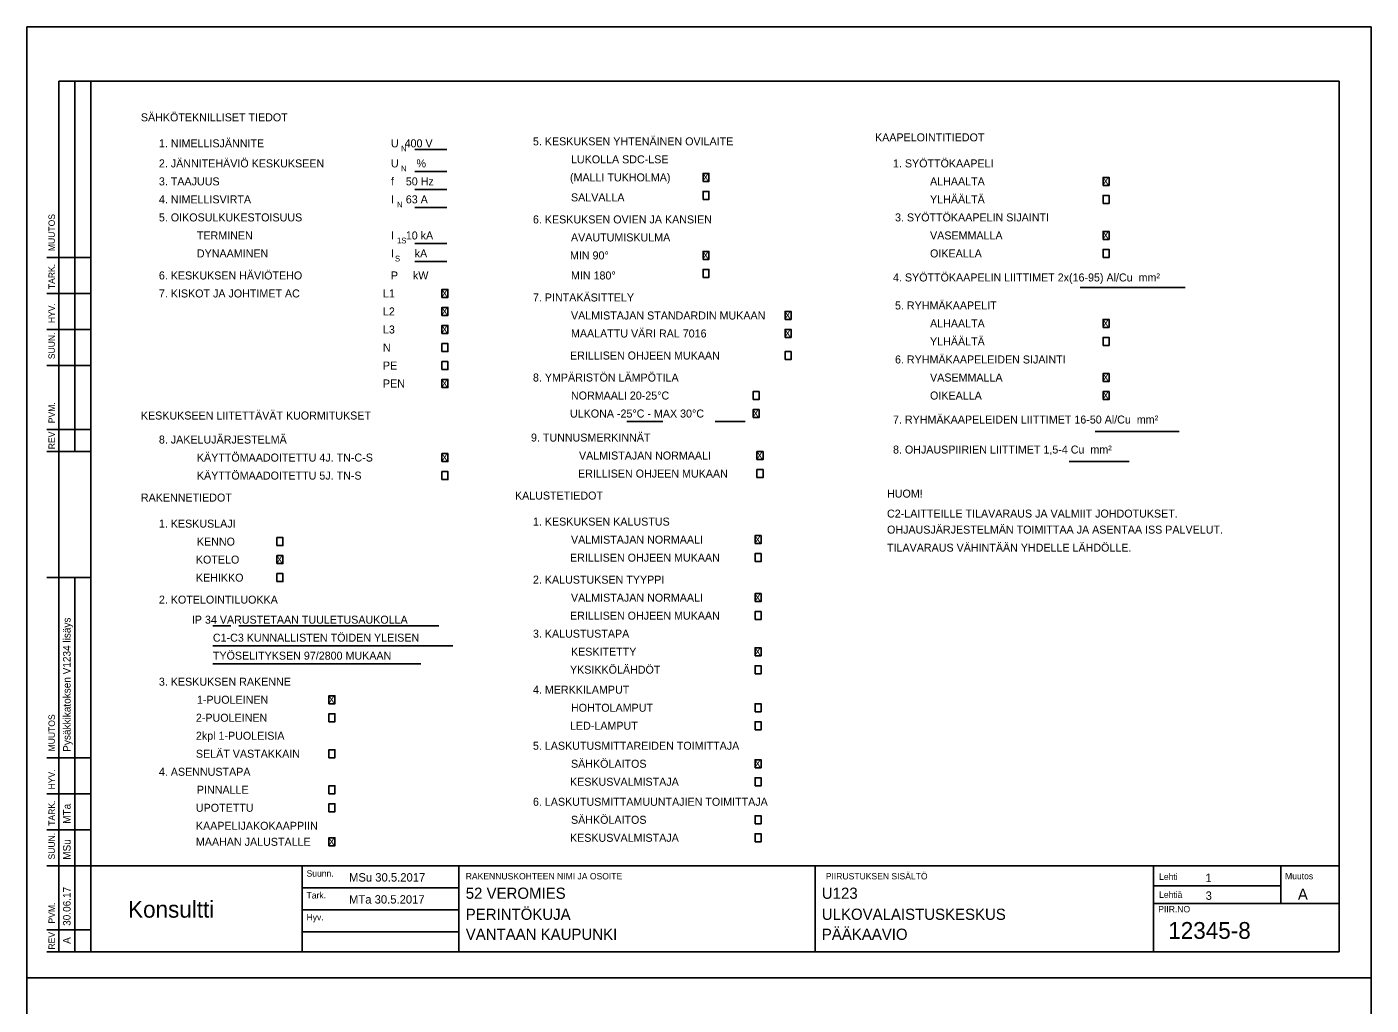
# Model space of a CAD drawing. Extents: x 0 to 420, y -594 to 297.
# Drawn here: x 0 to 420, y -8.5 to 297 of the extents above; entities that cross this region are included whole.
import ezdxf

# ---------------------------------------------------------------- set-up
doc = ezdxf.new("R2010")
doc.units = 0
doc.layers.add('TEKSTI', color=7, linetype='Continuous')

msp = doc.modelspace()

# ---------------------------------------------------------------- linework, layer by layer
for p, q in [((0, 297), (0, 0)), ((420, 297), (0, 297)), ((420, 0), (420, 297)), ((10, 280), (10, 8.12)), ((15, 164.38), (15, 280)), ((20, 280), (20, 8.12)), ((410, 280), (20, 280)), ((410, 8.12), (410, 280)), ((15, 8.12), (15, 125)), ((410, 32.5), (410, 85)), ((20, 35), (410, 35)), ((86, 35), (86, 8.12)), ((135, 35), (135, 8.12)), ((246.25, 8.12), (246.25, 35)), ((352, 8.12), (352, 35)), ((391.75, 23.22), (391.75, 35)), ((86, 28.12), (135, 28.12)), ((351.88, 28.75), (391.75, 28.75)), ((86, 21.25), (135, 21.25)), ((351.88, 23.2), (410, 23.2)), ((86, 14.38), (135, 14.38)), ((20, 8.12), (410, 8.12)), ((0, 0), (0, -297)), ((420, 0), (0, 0)), ((420, -297), (420, 0))]:
    msp.add_line(p, q)
for points in [[(10, 280), (20.14, 280)], [(121.25, 258.75), (131.25, 258.75)], [(121.25, 251.88), (131.25, 251.88)], [(211.25, 248.75), (213.12, 248.75), (213.12, 251.25), (211.25, 251.25), (211.25, 248.75)], [(336.25, 247.5), (338.12, 247.5), (338.12, 250), (336.25, 250), (336.25, 247.5)], [(121.25, 246.25), (131.25, 246.25)], [(211.25, 243.12), (213.12, 243.12), (213.12, 245.62), (211.25, 245.62), (211.25, 243.12)], [(336.25, 241.88), (338.12, 241.88), (338.12, 244.38), (336.25, 244.38), (336.25, 241.88)], [(121.25, 240.62), (131.25, 240.62)], [(336.25, 230.62), (338.12, 230.62), (338.12, 233.12), (336.25, 233.12), (336.25, 230.62)], [(121.25, 229.38), (131.25, 229.38)], [(211.25, 224.38), (213.12, 224.38), (213.12, 226.88), (211.25, 226.88), (211.25, 224.38)], [(336.25, 225), (338.12, 225), (338.12, 227.5), (336.25, 227.5), (336.25, 225)], [(6.25, 225), (20, 225)], [(121.25, 223.75), (131.25, 223.75)], [(211.25, 218.75), (213.12, 218.75), (213.12, 221.25), (211.25, 221.25), (211.25, 218.75)], [(129.69, 212.5), (131.56, 212.5), (131.56, 215), (129.69, 215), (129.69, 212.5)], [(329.06, 215.62), (361.88, 215.62)], [(6.25, 213.75), (20, 213.75)], [(129.69, 206.88), (131.56, 206.88), (131.56, 209.38), (129.69, 209.38), (129.69, 206.88)], [(236.88, 205.62), (238.75, 205.62), (238.75, 208.12), (236.88, 208.12), (236.88, 205.62)], [(6.25, 202.5), (20, 202.5)], [(129.69, 201.25), (131.56, 201.25), (131.56, 203.75), (129.69, 203.75), (129.69, 201.25)], [(236.88, 200), (238.75, 200), (238.75, 202.5), (236.88, 202.5), (236.88, 200)], [(336.25, 203.12), (338.12, 203.12), (338.12, 205.62), (336.25, 205.62), (336.25, 203.12)], [(129.69, 195.62), (131.56, 195.62), (131.56, 198.12), (129.69, 198.12), (129.69, 195.62)], [(336.25, 197.5), (338.12, 197.5), (338.12, 200), (336.25, 200), (336.25, 197.5)], [(236.88, 193.12), (238.75, 193.12), (238.75, 195.62), (236.88, 195.62), (236.88, 193.12)], [(6.25, 191.25), (20, 191.25)], [(129.69, 190), (131.56, 190), (131.56, 192.5), (129.69, 192.5), (129.69, 190)], [(129.69, 184.38), (131.56, 184.38), (131.56, 186.88), (129.69, 186.88), (129.69, 184.38)], [(336.25, 186.25), (338.12, 186.25), (338.12, 188.75), (336.25, 188.75), (336.25, 186.25)], [(226.88, 180.62), (228.75, 180.62), (228.75, 183.12), (226.88, 183.12), (226.88, 180.62)], [(336.25, 180.62), (338.12, 180.62), (338.12, 183.12), (336.25, 183.12), (336.25, 180.62)], [(226.88, 175), (228.75, 175), (228.75, 177.5), (226.88, 177.5), (226.88, 175)], [(187.5, 173.75), (198.75, 173.75)], [(215, 173.75), (224.38, 173.75)], [(6.25, 171.25), (20, 171.25)], [(333.75, 170.62), (360, 170.62)], [(6.25, 164.38), (20.14, 164.38)], [(228.12, 161.88), (230, 161.88), (230, 164.38), (228.12, 164.38), (228.12, 161.88)], [(129.69, 161.25), (131.56, 161.25), (131.56, 163.75), (129.69, 163.75), (129.69, 161.25)], [(325.62, 161.25), (344.38, 161.25)], [(129.69, 155.62), (131.56, 155.62), (131.56, 158.12), (129.69, 158.12), (129.69, 155.62)], [(228.12, 156.25), (230, 156.25), (230, 158.75), (228.12, 158.75), (228.12, 156.25)], [(78.12, 135), (80, 135), (80, 137.5), (78.12, 137.5), (78.12, 135)], [(227.5, 135.62), (229.38, 135.62), (229.38, 138.12), (227.5, 138.12), (227.5, 135.62)], [(78.12, 129.38), (80, 129.38), (80, 131.88), (78.12, 131.88), (78.12, 129.38)], [(227.5, 130), (229.38, 130), (229.38, 132.5), (227.5, 132.5), (227.5, 130)], [(78.12, 123.75), (80, 123.75), (80, 126.25), (78.12, 126.25), (78.12, 123.75)], [(6.25, 125), (20, 125)], [(227.5, 117.5), (229.38, 117.5), (229.38, 120), (227.5, 120), (227.5, 117.5)], [(227.5, 111.88), (229.38, 111.88), (229.38, 114.38), (227.5, 114.38), (227.5, 111.88)], [(63.75, 110), (58.12, 110)], [(66.25, 110), (128.75, 110)], [(58.12, 103.75), (133.12, 103.75)], [(227.5, 100.62), (229.38, 100.62), (229.38, 103.12), (227.5, 103.12), (227.5, 100.62)], [(58.12, 98.12), (123.12, 98.12)], [(227.5, 95), (229.38, 95), (229.38, 97.5), (227.5, 97.5), (227.5, 95)], [(94.38, 85.62), (96.25, 85.62), (96.25, 88.12), (94.38, 88.12), (94.38, 85.62)], [(227.5, 83.12), (229.38, 83.12), (229.38, 85.62), (227.5, 85.62), (227.5, 83.12)], [(94.38, 80), (96.25, 80), (96.25, 82.5), (94.38, 82.5), (94.38, 80)], [(227.5, 77.5), (229.38, 77.5), (229.38, 80), (227.5, 80), (227.5, 77.5)], [(6.25, 68.75), (20, 68.75)], [(94.38, 68.75), (96.25, 68.75), (96.25, 71.25), (94.38, 71.25), (94.38, 68.75)], [(227.5, 65.62), (229.38, 65.62), (229.38, 68.12), (227.5, 68.12), (227.5, 65.62)], [(94.38, 57.5), (96.25, 57.5), (96.25, 60), (94.38, 60), (94.38, 57.5)], [(227.5, 60), (229.38, 60), (229.38, 62.5), (227.5, 62.5), (227.5, 60)], [(6.25, 57.5), (20, 57.5)], [(94.38, 51.88), (96.25, 51.88), (96.25, 54.38), (94.38, 54.38), (94.38, 51.88)], [(227.5, 48.12), (229.38, 48.12), (229.38, 50.62), (227.5, 50.62), (227.5, 48.12)], [(6.25, 46.25), (20, 46.25)], [(94.38, 41.25), (96.25, 41.25), (96.25, 43.75), (94.38, 43.75), (94.38, 41.25)], [(227.5, 42.5), (229.38, 42.5), (229.38, 45), (227.5, 45), (227.5, 42.5)], [(6.25, 35), (20, 35)], [(6.25, 15), (20, 15)], [(20, 8.12), (6.25, 8.12)], [(0, 0), (420, 0)]]:
    msp.add_lwpolyline(points)

# ---------------------------------------------------------------- texts
for s, height, p in [('SÄHKÖTEKNILLISET TIEDOT', 2.5, (35.62, 267.5)), ('1. NIMELLISJÄNNITE', 2.5, (41.25, 259.38)), ('U  400 V', 2.5, (113.75, 259.38)), ('5. KESKUKSEN YHTENÄINEN OVILAITE', 2.5, (158.12, 260)), ('KAAPELOINTITIEDOT', 2.5, (265, 261.25)), ('N', 1.8, (116.88, 258.12)), ('LUKOLLA SDC-LSE', 2.5, (170, 254.38)), ('2. JÄNNITEHÄVIÖ KESKUKSEEN', 2.5, (41.25, 253.12)), ('U      %%%', 2.5, (113.75, 253.12)), ('N', 1.8, (116.88, 251.88)), ('1. SYÖTTÖKAAPELI', 2.5, (270.62, 253.12)), ('3. TAAJUUS', 2.5, (41.25, 247.5)), ('f    50 Hz', 2.5, (113.75, 247.5)), ('(MALLI TUKHOLMA)', 2.5, (169.69, 248.75)), ('X', 2.5, (210.94, 248.75)), ('ALHAALTA', 2.5, (282.19, 247.5)), ('X', 2.5, (335.94, 247.5)), ('4. NIMELLISVIRTA', 2.5, (41.25, 241.88)), ('I    63 A', 2.5, (113.75, 241.88)), ('SALVALLA', 2.5, (170, 242.5)), ('YLHÄÄLTÄ', 2.5, (282.19, 241.88)), ('N', 1.8, (115.62, 240.62)), ('5. OIKOSULKUKESTOISUUS', 2.5, (41.25, 236.25)), ('6. KESKUKSEN OVIEN JA KANSIEN', 2.5, (158.12, 235.62)), ('3. SYÖTTÖKAAPELIN SIJAINTI', 2.5, (271.25, 236.25)), ('TERMINEN', 2.5, (53.12, 230.62)), ('I    10 kA', 2.5, (113.75, 230.62)), ('1S', 1.8, (115.62, 229.38)), ('AVAUTUMISKULMA', 2.5, (170, 230)), ('VASEMMALLA', 2.5, (282.19, 230.62)), ('X', 2.5, (335.94, 230.62)), ('DYNAAMINEN', 2.5, (53.12, 225)), ('I       kA', 2.5, (113.75, 225)), ('MIN 90°', 2.5, (169.69, 224.38)), ('X', 2.5, (210.94, 224.38)), ('OIKEALLA', 2.5, (282.19, 225)), ('S', 1.8, (115, 223.75)), ('6. KESKUKSEN HÄVIÖTEHO', 2.5, (41.25, 218.12)), ('P     kW', 2.5, (113.75, 218.12)), ('MIN 180°', 2.5, (170, 218.12)), ('4. SYÖTTÖKAAPELIN LIITTIMET 2x(16-95) Al/Cu  mm²  ', 2.5, (270.62, 217.5)), ('7. KISKOT JA JOHTIMET AC', 2.5, (41.25, 212.5)), ('L1', 2.5, (111.25, 212.5)), ('X', 2.5, (129.38, 212.5)), ('7. PINTAKÄSITTELY', 2.5, (158.12, 211.25)), ('5. RYHMÄKAAPELIT', 2.5, (271.25, 208.75)), ('L2', 2.5, (111.25, 206.88)), ('X', 2.5, (129.38, 206.88)), ('VALMISTAJAN STANDARDIN MUKAAN', 2.5, (170, 205.62)), ('X', 2.5, (236.56, 205.62)), ('L3', 2.5, (111.25, 201.25)), ('X', 2.5, (129.38, 201.25)), ('MAALATTU VÄRI RAL 7016', 2.5, (170, 200)), ('X', 2.5, (236.56, 200)), ('ALHAALTA', 2.5, (282.19, 203.12)), ('X', 2.5, (335.94, 203.12)), ('N', 2.5, (111.25, 195.62)), ('YLHÄÄLTÄ', 2.5, (282.19, 197.5)), ('ERILLISEN OHJEEN MUKAAN', 2.5, (169.69, 193.12)), ('6. RYHMÄKAAPELEIDEN SIJAINTI', 2.5, (271.25, 191.88)), ('PE', 2.5, (111.25, 190)), ('8. YMPÄRISTÖN LÄMPÖTILA', 2.5, (158.12, 186.25)), ('PEN', 2.5, (111.25, 184.38)), ('X', 2.5, (129.38, 184.38)), ('VASEMMALLA', 2.5, (282.19, 186.25)), ('X', 2.5, (335.94, 186.25)), ('NORMAALI 20-25°C', 2.5, (170, 180.62)), ('OIKEALLA', 2.5, (282.19, 180.62)), ('X', 2.5, (335.94, 180.62)), ('KESKUKSEEN LIITETTÄVÄT KUORMITUKSET', 2.5, (35.62, 174.38)), ('ULKONA -25°C - MAX 30°C', 2.5, (169.69, 175)), ('X', 2.5, (226.56, 175)), ('7. RYHMÄKAAPELEIDEN LIITTIMET 16-50 Al/Cu  mm²  ', 2.5, (270.62, 173.12)), ('8. JAKELUJÄRJESTELMÄ', 2.5, (41.25, 166.88)), ('9. TUNNUSMERKINNÄT', 2.5, (157.5, 167.5)), ('KÄYTTÖMAADOITETTU 4J. TN-C-S', 2.5, (53.12, 161.25)), ('VALMISTAJAN NORMAALI', 2.5, (172.5, 161.88)), ('X', 2.5, (227.81, 161.88)), ('8. OHJAUSPIIRIEN LIITTIMET 1,5-4 Cu  mm²  ', 2.5, (270.62, 163.75)), ('X', 2.5, (129.38, 161.25)), ('KÄYTTÖMAADOITETTU 5J. TN-S', 2.5, (53.12, 155.62)), ('ERILLISEN OHJEEN MUKAAN', 2.5, (172.19, 156.25)), ('RAKENNETIEDOT', 2.5, (35.62, 148.75)), ('KALUSTETIEDOT', 2.5, (152.5, 149.38)), ('HUOM!', 2.5, (268.75, 150)), ('1. KESKUSLAJI', 2.5, (41.25, 140.62)), ('1. KESKUKSEN KALUSTUS', 2.5, (158.12, 141.25)), ('C2-LAITTEILLE TILAVARAUS JA VALMIIT JOHDOTUKSET.', 2.5, (268.75, 143.75)), ('OHJAUSJÄRJESTELMÄN TOIMITTAA JA ASENTAA ISS PALVELUT.', 2.5, (268.75, 138.75)), ('KENNO', 2.5, (53.12, 135)), ('VALMISTAJAN NORMAALI', 2.5, (170, 135.62)), ('X', 2.5, (227.19, 135.62)), ('TILAVARAUS VÄHINTÄÄN YHDELLE LÄHDÖLLE.', 2.5, (268.75, 133.12)), ('KOTELO', 2.5, (52.81, 129.38)), ('X', 2.5, (77.81, 129.38)), ('ERILLISEN OHJEEN MUKAAN', 2.5, (169.69, 130)), ('KEHIKKO', 2.5, (52.81, 123.75)), ('2. KALUSTUKSEN TYYPPI', 2.5, (158.12, 123.12)), ('2. KOTELOINTILUOKKA', 2.5, (41.25, 116.88)), ('VALMISTAJAN NORMAALI', 2.5, (170, 117.5)), ('X', 2.5, (227.19, 117.5)), ('ERILLISEN OHJEEN MUKAAN', 2.5, (169.69, 111.88)), (' IP 34 VARUSTETAAN TUULETUSAUKOLLA', 2.5, (50.62, 110.62)), ('C1-C3 KUNNALLISTEN TÖIDEN YLEISEN', 2.5, (58.12, 105)), ('3. KALUSTUSTAPA', 2.5, (158.12, 106.25)), ('TYÖSELITYKSEN 97/2800 MUKAAN', 2.5, (58.12, 99.38)), ('KESKITETTY', 2.5, (170, 100.62)), ('X', 2.5, (227.19, 100.62)), ('YKSIKKÖLÄHDÖT', 2.5, (169.69, 95)), ('3. KESKUKSEN RAKENNE', 2.5, (41.25, 91.25)), ('4. MERKKILAMPUT', 2.5, (158.12, 88.75)), ('1-PUOLEINEN', 2.5, (53.12, 85.62)), ('X', 2.5, (94.06, 85.62)), ('HOHTOLAMPUT', 2.5, (170, 83.12)), ('2-PUOLEINEN', 2.5, (52.81, 80)), ('LED-LAMPUT', 2.5, (169.69, 77.5)), ('2kpl 1-PUOLEISIA', 2.5, (52.81, 74.38)), ('SELÄT VASTAKKAIN', 2.5, (52.81, 68.75)), ('5. LASKUTUSMITTAREIDEN TOIMITTAJA', 2.5, (158.12, 71.25)), ('SÄHKÖLAITOS', 2.5, (170, 65.62)), ('X', 2.5, (227.19, 65.62)), ('4. ASENNUSTAPA', 2.5, (41.25, 63.12)), ('PINNALLE', 2.5, (53.12, 57.5)), ('KESKUSVALMISTAJA', 2.5, (169.69, 60)), ('6. LASKUTUSMITTAMUUNTAJIEN TOIMITTAJA', 2.5, (158.12, 53.75)), ('UPOTETTU', 2.5, (52.81, 51.88)), ('SÄHKÖLAITOS', 2.5, (170, 48.12)), ('KAAPELIJAKOKAAPPIIN', 2.5, (52.81, 46.25)), ('MAAHAN JALUSTALLE', 2.5, (52.81, 41.25)), ('X', 2.5, (94.06, 41.25)), ('KESKUSVALMISTAJA', 2.5, (169.69, 42.5)), ('Suunn.', 2, (87.38, 31.62)), ('MSu 30.5.2017', 2.625, (100.66, 30.08)), ('RAKENNUSKOHTEEN NIMI JA OSOITE', 2, (137.12, 30.75)), ('PIIRUSTUKSEN SISÄLTÖ', 2, (249.62, 30.75)), ('Lehti', 2, (353.75, 30.62)), ('1', 2.62, (368.21, 29.92)), ('Muutos', 2, (393.12, 30.79)), ('Tark.', 2, (87.38, 24.8)), ('MTa 30.5.2017', 2.625, (100.66, 23.2)), ('52 VEROMIES', 3.5, (137.12, 24.69)), ('U123', 3.5, (248.38, 24.69)), ('Lehtiä', 2, (353.75, 25)), ('3', 2.62, (368.31, 24.38)), ('A', 3.5, (397.12, 24.38)), ('Konsultti', 5.25, (31.62, 18.81)), ('PERINTÖKUJA', 3.5, (137.12, 18.12)), ('ULKOVALAISTUSKESKUS', 3.5, (248.38, 18.12)), ('PIIR.NO', 2, (353.5, 20.45)), ('Hyv.', 2, (87.38, 17.93)), ('12345-8', 5.25, (356.62, 12.19)), ('VANTAAN KAUPUNKI', 3.5, (137.12, 11.88)), ('PÄÄKAAVIO', 3.5, (248.38, 11.88))]:
    msp.add_text(s, height=height).set_placement(p)
for s, p in [('MUUTOS', (8.75, 226.97)), ('TARK.', (8.75, 215.1)), ('HYV.', (8.75, 204.47)), ('SUUN.', (8.75, 193.22)), ('PVM.', (8.75, 173.22)), ('REV', (8.75, 165.1)), ('MUUTOS', (8.75, 70.72)), ('HYV.', (8.75, 58.85)), ('TARK.', (8.75, 47.5)), ('SUUN.', (8.75, 36.97)), ('PVM.', (8.75, 16.97)), ('REV', (8.75, 8.85))]:
    msp.add_text(s, height=2, rotation=90).set_placement(p)
at = {"layer": 'TEKSTI'}
for s, p in [('Pysäkkikatoksen V1234 lisäys', (13.65, 70.62)), ('MTa', (13.65, 48.12)), ('MSu', (13.65, 36.88)), ('30.06.17', (13.65, 16.25)), ('A', (13.65, 10.62))]:
    msp.add_text(s, height=2.34, rotation=90, dxfattribs=at).set_placement(p)

doc.saveas('drawing.dxf')
